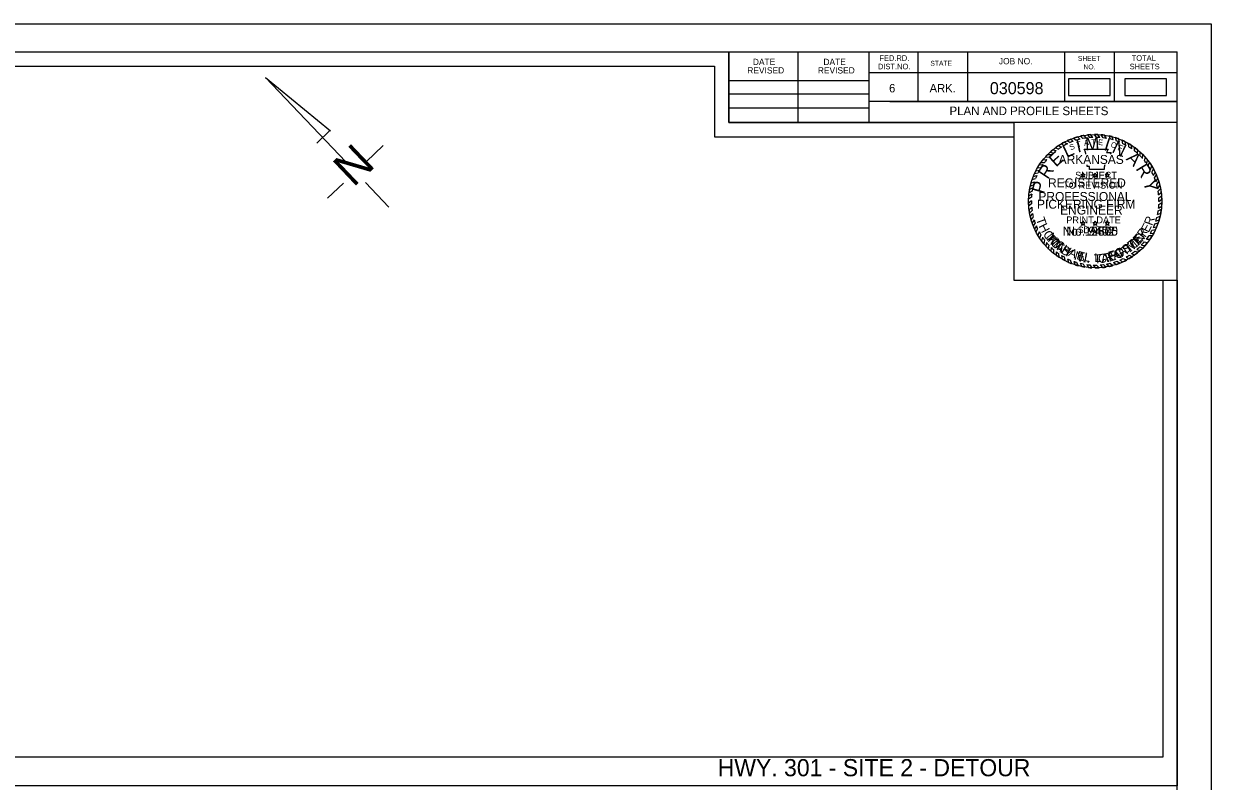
# Model space of a CAD drawing. Extents: x 816090 to 819714, y 1801340 to 1803641.
# Drawn here: x 818885 to 819714, y 1801878 to 1802407 of the extents above; entities that cross this region are included whole.
import ezdxf

# ---------------------------------------------------------------- set-up
doc = ezdxf.new("R2010")
doc.units = 0
for name, color, linetype in [('R_Border', 7, 'Continuous'), ('R_Border Notes', 7, 'Continuous'), ('R_Border Title', 7, 'Continuous'), ('R_Draft', 7, 'Continuous'), ('R_No Plot', 7, 'Continuous'), ('R_Vert Alg Annot', 7, 'Continuous'), ('STAMP_PE_CRAFTON', 7, 'Continuous'), ('STAMP_PE_FOSTER', 7, 'Continuous'), ('STAMP_PE_SEAL-INFO', 7, 'Continuous'), ('STAMP_PE_TAEGTMEYER', 7, 'Continuous'), ('STAMP_PE_TXT', 7, 'Continuous'), ('STAMP_PRELIMINARY', 7, 'Continuous')]:
    doc.layers.add(name, color=color, linetype=linetype)

msp = doc.modelspace()

# ---------------------------------------------------------------- linework, layer by layer
at = {"layer": 'R_Border'}
for p, q in [((818109.59, 1802387.13), (819690.49, 1802387.13)), ((819377.29, 1802337.73), (819377.29, 1802387.13)), ((819425.69, 1802337.73), (819425.69, 1802387.13)), ((819474.99, 1802387.13), (819474.99, 1802337.73)), ((819509.19, 1802387.13), (819509.19, 1802352.43)), ((819543.89, 1802387.13), (819543.89, 1802352.43)), ((819611.79, 1802387.13), (819611.79, 1802352.43)), ((819646.49, 1802387.13), (819646.49, 1802352.43)), ((819690.49, 1801359.83), (819690.49, 1802387.13)), ((819377.29, 1802367.03), (819474.99, 1802367.03)), ((819690.49, 1802372.43), (819474.99, 1802372.43)), ((819690.49, 1802372.53), (819690.49, 1802372.53)), ((819377.29, 1802357.73), (819474.99, 1802357.73)), ((819690.49, 1802352.43), (819474.99, 1802352.43)), ((819489.79, 1802352.43), (819690.49, 1802352.43)), ((819377.29, 1802348.03), (819474.99, 1802348.03)), ((819690.49, 1802337.73), (819377.29, 1802337.73))]:
    msp.add_line(p, q, dxfattribs=at)
at = {"layer": 'R_Draft'}
for p, q in [((819053.53, 1802369.08), (819098.93, 1802331.97)), ((819109.63, 1802310.17), (819053.53, 1802369.08)), ((819089.27, 1802323.37), (819098.63, 1802332.28)), ((819123.68, 1802310.31), (819135.62, 1802321.67)), ((819096.87, 1802284.77), (819108.04, 1802295.41)), ((819139.72, 1802278.56), (819123.23, 1802295.89))]:
    msp.add_line(p, q, dxfattribs=at)
at = {"layer": 'R_No Plot'}
msp.add_line((818047.58, 1802406.6), (819714.25, 1802406.6), dxfattribs=at)
for points in [[(818047.58, 1802406.62), (819714.28, 1802406.62), (819714.28, 1801339.93), (818047.58, 1801339.93)], [(819377.29, 1802387.13), (819377.29, 1802337.73), (819457.85, 1802337.73), (819576.4, 1802337.73), (819576.4, 1802227.73), (819690.49, 1802227.73), (819690.49, 1801874.53), (818109.59, 1801874.53), (818109.59, 1802387.13)], [(819680.49, 1801894.53), (818119.59, 1801894.53), (818119.59, 1802377.13), (819367.29, 1802377.13), (819367.29, 1802327.73), (819576.4, 1802327.73), (819576.4, 1802227.73), (819680.49, 1802227.73)], [(819680.49, 1801894.53), (818119.59, 1801894.53), (818119.59, 1802377.13), (819367.29, 1802377.13), (819367.29, 1802327.73), (819576.4, 1802327.73), (819576.4, 1802227.73), (819680.49, 1802227.73)], [(819680.49, 1801894.53), (818119.59, 1801894.53), (818119.59, 1802377.13), (819367.29, 1802377.13), (819367.29, 1802327.73), (819576.4, 1802327.73), (819576.4, 1802227.73), (819680.49, 1802227.73)], [(819690.49, 1802337.73), (819576.4, 1802337.73), (819576.4, 1802227.73), (819690.49, 1802227.73)]]:
    msp.add_lwpolyline(points, close=True, dxfattribs=at)
at = {"layer": 'R_Vert Alg Annot'}
for points in [[(819614.55, 1802356.65), (819643.72, 1802356.65), (819643.72, 1802368.2), (819614.55, 1802368.2)], [(819653.9, 1802356.65), (819683.07, 1802356.65), (819683.07, 1802368.2), (819653.9, 1802368.2)]]:
    msp.add_lwpolyline(points, close=True, dxfattribs=at)
at = {"layer": 'STAMP_PE_SEAL-INFO'}
for p, q in [((819613.7, 1802325.07), (819615.65, 1802323.7)), ((819616.24, 1802326.15), (819617.71, 1802324.52)), ((819617.98, 1802326.79), (819619.88, 1802325.26)), ((819620.93, 1802327.7), (819622.37, 1802325.96)), ((819622.87, 1802328.18), (819624.65, 1802326.47)), ((819625.28, 1802328.67), (819626.78, 1802326.83)), ((819627.86, 1802329.03), (819629.27, 1802327.12)), ((819631.54, 1802327.26), (819629.98, 1802329.23)), ((819634.03, 1802327.29), (819632.63, 1802329.34)), ((819636.32, 1802327.18), (819635.03, 1802329.3)), ((819638.85, 1802326.93), (819637.39, 1802329.15)), ((819640.98, 1802326.61), (819639.69, 1802328.88)), ((819643.79, 1802326.01), (819642.92, 1802328.31)), ((819645.8, 1802325.47), (819645, 1802327.82)), ((819648.05, 1802324.74), (819647.35, 1802327.13)), ((819650.15, 1802323.94), (819649.42, 1802326.42)), ((819652.45, 1802322.91), (819651.94, 1802325.4)), ((819654.68, 1802321.76), (819654.25, 1802324.31)), ((819601.67, 1802317.07), (819603.96, 1802316.38)), ((819603.38, 1802318.57), (819606.03, 1802318.07)), ((819605.27, 1802320.21), (819607.55, 1802319.18)), ((819607.37, 1802321.54), (819609.58, 1802320.53)), ((819609.31, 1802322.76), (819611.47, 1802321.65)), ((819611.55, 1802324.01), (819613.86, 1802322.89)), ((819625.54, 1802319.18), (819642.27, 1802319.18)), ((819626.15, 1802317.65), (819625.54, 1802319.18)), ((819626.67, 1802316.16), (819626.15, 1802317.65)), ((819626.71, 1802315.58), (819626.67, 1802316.16)), ((819642.27, 1802319.18), (819641.14, 1802316.72)), ((819641.14, 1802316.72), (819644.3, 1802316.72)), ((819644.3, 1802316.72), (819643.58, 1802315.58)), ((819656.62, 1802320.63), (819656.42, 1802323.13)), ((819658.79, 1802319.2), (819658.64, 1802321.77)), ((819660.59, 1802317.86), (819660.77, 1802320.3)), ((819662.83, 1802316), (819662.92, 1802318.62)), ((819664.39, 1802314.54), (819664.74, 1802317.03)), ((819594.08, 1802308.11), (819596.66, 1802308.28)), ((819595.26, 1802309.83), (819597.78, 1802309.8)), ((819596.65, 1802311.68), (819599.39, 1802311.79)), ((819598.38, 1802313.73), (819600.98, 1802313.54)), ((819599.99, 1802315.45), (819602.71, 1802315.25)), ((819627.66, 1802307.04), (819627.53, 1802308.13)), ((819639.85, 1802308.13), (819639.46, 1802306.58)), ((819666.18, 1802312.67), (819666.52, 1802315.3)), ((819667.55, 1802311.09), (819668.24, 1802313.45)), ((819669.17, 1802309.01), (819669.85, 1802311.5)), ((819670.27, 1802307.43), (819671.16, 1802309.75)), ((819589.84, 1802299.88), (819592.36, 1802300.61)), ((819590.76, 1802302.04), (819593.27, 1802302.56)), ((819591.7, 1802303.99), (819594.19, 1802304.31)), ((819592.85, 1802306.1), (819595.3, 1802306.2)), ((819629.23, 1802307.04), (819627.66, 1802307.04)), ((819629.23, 1802304.89), (819629.23, 1802307.04)), ((819639.38, 1802304.89), (819629.23, 1802304.89)), ((819639.46, 1802306.58), (819639.38, 1802304.89)), ((819671.81, 1802304.94), (819672.73, 1802307.4)), ((819672.81, 1802303.11), (819673.94, 1802305.33)), ((819673.97, 1802300.69), (819675.1, 1802303.12)), ((819674.67, 1802299.01), (819675.99, 1802301.17)), ((819589.6, 1802292.06), (819587.27, 1802290.82)), ((819587.78, 1802293.3), (819590.13, 1802294.26)), ((819588.3, 1802295.33), (819590.69, 1802296.18)), ((819589.09, 1802297.85), (819591.51, 1802298.53)), ((819675.64, 1802296.26), (819677, 1802298.63)), ((819676.18, 1802294.44), (819677.65, 1802296.7)), ((819676.85, 1802291.64), (819678.44, 1802293.88)), ((819677.19, 1802289.74), (819678.96, 1802291.51)), ((819588.7, 1802285.47), (819586.59, 1802284.18)), ((819588.61, 1802283), (819586.59, 1802281.32)), ((819588.88, 1802287.59), (819586.7, 1802286.19)), ((819589.17, 1802289.77), (819586.95, 1802288.66)), ((819677.52, 1802287.2), (819679.39, 1802288.88)), ((819677.68, 1802285.11), (819679.64, 1802286.57)), ((819677.75, 1802282.52), (819679.77, 1802284.13)), ((819588.65, 1802280.97), (819586.69, 1802279.34)), ((819588.81, 1802278.49), (819586.96, 1802276.71)), ((819589.07, 1802276.34), (819587.3, 1802274.48)), ((819676.79, 1802273.52), (819679.06, 1802274.5)), ((819677.24, 1802276.02), (819679.45, 1802277.12)), ((819677.49, 1802277.96), (819679.66, 1802279.24)), ((819677.69, 1802280.49), (819679.79, 1802281.88)), ((819589.47, 1802274.05), (819587.77, 1802272.21)), ((819589.93, 1802271.95), (819588.37, 1802269.88)), ((819590.55, 1802269.72), (819589.08, 1802267.63)), ((819591.26, 1802267.6), (819589.85, 1802265.54)), ((819674.84, 1802266.89), (819677.25, 1802267.54)), ((819675.51, 1802268.79), (819677.96, 1802269.79)), ((819676.25, 1802271.26), (819678.61, 1802272.27)), ((819592.09, 1802265.47), (819590.78, 1802263.36)), ((819592.95, 1802263.55), (819591.81, 1802261.25)), ((819594.12, 1802261.26), (819593.17, 1802258.81)), ((819595.3, 1802259.24), (819594.38, 1802256.89)), ((819670.74, 1802258.74), (819673.13, 1802258.71)), ((819671.6, 1802260.14), (819674.11, 1802260.41)), ((819672.96, 1802262.64), (819675.4, 1802262.98)), ((819673.77, 1802264.32), (819676.21, 1802264.8)), ((819596.31, 1802257.69), (819595.76, 1802254.93)), ((819597.72, 1802255.73), (819597.21, 1802253.08)), ((819599.24, 1802253.85), (819598.8, 1802251.25)), ((819600.75, 1802252.16), (819600.44, 1802249.55)), ((819602.36, 1802250.53), (819602.21, 1802247.89)), ((819664.32, 1802250.84), (819666.52, 1802250.15)), ((819665.59, 1802252.13), (819667.98, 1802251.71)), ((819667.51, 1802254.3), (819669.81, 1802253.9)), ((819669.05, 1802256.27), (819671.57, 1802256.28)), ((819604.08, 1802248.97), (819604.07, 1802246.32)), ((819605.88, 1802247.5), (819605.98, 1802244.87)), ((819607.57, 1802246.25), (819607.76, 1802243.66)), ((819609.71, 1802244.84), (819610.01, 1802242.28)), ((819611.46, 1802243.81), (819611.92, 1802241.24)), ((819613.87, 1802242.56), (819614.65, 1802239.95)), ((819615.73, 1802241.72), (819616.59, 1802239.16)), ((819650.5, 1802241.66), (819652.62, 1802240.36)), ((819652.8, 1802242.71), (819655.22, 1802241.65)), ((819654.84, 1802243.77), (819656.92, 1802242.61)), ((819656.91, 1802245), (819659.16, 1802244.02)), ((819658.63, 1802246.14), (819660.82, 1802245.19)), ((819660.93, 1802247.85), (819663.27, 1802247.13)), ((819662.29, 1802248.98), (819664.64, 1802248.33)), ((819618.19, 1802240.75), (819619.24, 1802238.25)), ((819620.24, 1802240.08), (819621.37, 1802237.63)), ((819622.78, 1802239.39), (819623.84, 1802237.06)), ((819624.77, 1802238.96), (819626, 1802236.67)), ((819627.27, 1802238.55), (819628.47, 1802236.35)), ((819629.45, 1802238.31), (819630.82, 1802236.17)), ((819631.87, 1802238.18), (819633.39, 1802236.11)), ((819634.17, 1802238.17), (819635.89, 1802236.19)), ((819636.77, 1802238.3), (819638.4, 1802236.4)), ((819638.96, 1802238.53), (819640.82, 1802236.74)), ((819641.18, 1802238.88), (819643.13, 1802237.19)), ((819643.65, 1802239.4), (819645.54, 1802237.78)), ((819645.94, 1802240.02), (819648.03, 1802238.54)), ((819648.41, 1802240.84), (819650.62, 1802239.5))]:
    msp.add_line(p, q, dxfattribs=at)
for radius, start, end in [(46.61, 111.31242, 114.70259), (44.57, 110.30864, 113.16588), (46.61, 105.23389, 109.03519), (44.57, 104.03521, 107.36155), (46.61, 99.75254, 102.77648), (44.57, 98.25799, 101.03289), (46.61, 93.93815, 96.55172), (44.57, 92.11016, 95.03666), (46.61, 87.72979, 90.67067), (44.57, 85.96279, 88.9097), (46.61, 81.97315, 84.82355), (44.57, 79.92642, 82.69597), (46.61, 75.31251, 77.94263), (44.57, 73.55748, 76.23144), (46.61, 69.60611, 72.30577), (44.57, 67.62483, 70.50398), (46.61, 63.13288, 66.2704), (46.61, 129.73259, 132.53764), (44.57, 127.52969, 130.96829), (46.61, 123.61993, 126.59063), (44.57, 121.97456, 125.11001), (46.61, 117.65441, 120.80988), (44.57, 115.68692, 119.15827), (44.57, 61.15575, 64.37837), (46.61, 56.90029, 60.09423), (44.57, 54.92383, 58.27016), (44.57, 48.30163, 52.03953), (46.61, 50.3492, 53.71593), (46.61, 44.3405, 47.39292), (46.61, 147.00719, 149.89904), (46.61, 141.60556, 144.44865), (44.57, 145.01972, 148.21036), (44.57, 139.30101, 142.58729), (46.61, 135.40208, 138.30314), (44.57, 133.13306, 136.25623), (44.57, 42.22116, 45.55119), (44.57, 36.13503, 39.53106), (46.61, 38.12472, 41.23157), (46.61, 31.96138, 35.42937), (46.61, 158.40766, 161.07015), (46.61, 152.86398, 155.51889), (44.57, 156.34018, 159.23194), (44.57, 151.03153, 153.57304), (44.57, 29.90321, 33.66454), (44.57, 23.77322, 27.22114), (46.61, 25.93909, 29.01247), (46.61, 19.95381, 23.31409), (46.61, 164.3068, 166.89395), (44.57, 167.90481, 170.90393), (44.57, 162.43309, 165.00133), (44.57, 17.68022, 21.42509), (44.57, 11.54445, 15.23639), (46.61, 13.84205, 17.44468), (46.61, 7.58519, 10.86211), (46.61, 175.74093, 178.2066), (46.61, 170.0003, 172.68778), (44.57, 179.64537, 182.26333), (44.57, 173.73, 176.47337), (44.57, 5.7599, 9.06056), (44.57, 359.73289, 3.06392), (46.61, 1.72155, 4.72681), (46.61, 181.72508, 184.16255), (46.61, 187.42037, 190.19271), (44.57, 185.45389, 188.23401), (44.57, 348.07782, 351.34355), (44.57, 353.86319, 357.12742), (46.61, 349.83047, 353.08845), (46.61, 355.71562, 358.95694), (46.61, 193.03695, 195.99732), (46.61, 198.89671, 201.62812), (44.57, 191.22736, 193.98583), (44.57, 196.96751, 199.83526), (44.57, 335.6038, 339.18578), (44.57, 341.77699, 345.09248), (46.61, 337.38367, 340.99332), (46.61, 343.89247, 347.03502), (46.61, 204.54793, 207.43282), (44.57, 202.77613, 205.47915), (46.61, 210.86355, 213.65709), (44.57, 208.78826, 211.79343), (44.57, 323.58513, 327.44069), (46.61, 325.44052, 328.98725), (44.57, 329.55488, 333.20757), (46.61, 331.40371, 334.93315), (46.61, 216.61154, 219.49098), (44.57, 214.18375, 217.27474), (46.61, 222.47995, 225.38008), (44.57, 220.39088, 223.30564), (44.57, 226.24938, 229.24068), (44.57, 310.77436, 314.31605), (46.61, 312.45177, 315.66328), (44.57, 316.65308, 320.37109), (46.61, 318.28455, 321.80429), (46.61, 228.36648, 231.34802), (44.57, 232.22904, 234.93361), (46.61, 234.29502, 236.94517), (44.57, 238.22227, 240.83529), (46.61, 240.1977, 242.86128), (44.57, 244.32043, 246.94859), (44.57, 292.87452, 296.11851), (46.61, 294.64808, 298.21662), (44.57, 299.07679, 302.17235), (46.61, 300.62101, 303.87026), (44.57, 304.82299, 308.51428), (46.61, 306.37206, 310.20799), (46.61, 246.57598, 249.15579), (44.57, 250.34912, 253.12157), (46.61, 252.59667, 255.32518), (44.57, 256.50505, 259.11916), (46.61, 258.44328, 261.13983), (44.57, 262.37828, 265.20115), (46.61, 264.19784, 267.10092), (44.57, 268.3215, 271.27698), (46.61, 270.25484, 273.33609), (44.57, 274.61565, 277.44863), (46.61, 276.42389, 279.43574), (44.57, 280.34588, 283.58137), (46.61, 282.31994, 285.37019), (44.57, 286.64233, 289.97826), (46.61, 288.57086, 291.97334)]:
    msp.add_arc((819633.18, 1802282.73), radius, start, end, dxfattribs=at)
at = {"layer": 'STAMP_PE_TXT'}
for p, q in [((819624.08, 1802300.58), (819623.09, 1802301.3)), ((819623.09, 1802301.3), (819624.31, 1802301.3)), ((819623.7, 1802299.42), (819624.08, 1802300.58)), ((819624.69, 1802300.14), (819623.7, 1802299.42)), ((819624.31, 1802301.3), (819624.69, 1802302.47)), ((819624.69, 1802302.47), (819625.07, 1802301.3)), ((819625.68, 1802299.42), (819624.69, 1802300.14)), ((819625.07, 1802301.3), (819626.3, 1802301.3)), ((819626.3, 1802301.3), (819625.3, 1802300.58)), ((819625.3, 1802300.58), (819625.68, 1802299.42)), ((819632.57, 1802300.58), (819631.58, 1802301.3)), ((819631.58, 1802301.3), (819632.8, 1802301.3)), ((819632.19, 1802299.42), (819632.57, 1802300.58)), ((819633.18, 1802300.14), (819632.19, 1802299.42)), ((819632.8, 1802301.3), (819633.18, 1802302.47)), ((819633.18, 1802302.47), (819633.56, 1802301.3)), ((819634.17, 1802299.42), (819633.18, 1802300.14)), ((819633.56, 1802301.3), (819634.79, 1802301.3)), ((819634.79, 1802301.3), (819633.79, 1802300.58)), ((819633.79, 1802300.58), (819634.17, 1802299.42)), ((819641.06, 1802300.58), (819640.07, 1802301.3)), ((819640.07, 1802301.3), (819641.29, 1802301.3)), ((819640.68, 1802299.42), (819641.06, 1802300.58)), ((819641.67, 1802300.14), (819640.68, 1802299.42)), ((819641.29, 1802301.3), (819641.67, 1802302.47)), ((819641.67, 1802302.47), (819642.05, 1802301.3)), ((819642.66, 1802299.42), (819641.67, 1802300.14)), ((819642.05, 1802301.3), (819643.27, 1802301.3)), ((819643.27, 1802301.3), (819642.28, 1802300.58)), ((819642.28, 1802300.58), (819642.66, 1802299.42)), ((819624.08, 1802267.05), (819623.09, 1802267.77)), ((819623.09, 1802267.77), (819624.31, 1802267.77)), ((819623.7, 1802265.88), (819624.08, 1802267.05)), ((819624.69, 1802266.6), (819623.7, 1802265.88)), ((819624.31, 1802267.77), (819624.69, 1802268.93)), ((819624.69, 1802268.93), (819625.07, 1802267.77)), ((819625.68, 1802265.88), (819624.69, 1802266.6)), ((819625.07, 1802267.77), (819626.3, 1802267.77)), ((819626.3, 1802267.77), (819625.3, 1802267.05)), ((819625.3, 1802267.05), (819625.68, 1802265.88)), ((819632.57, 1802267.05), (819631.58, 1802267.77)), ((819631.58, 1802267.77), (819632.8, 1802267.77)), ((819632.19, 1802265.88), (819632.57, 1802267.05)), ((819633.18, 1802266.6), (819632.19, 1802265.88)), ((819632.8, 1802267.77), (819633.18, 1802268.93)), ((819633.18, 1802268.93), (819633.56, 1802267.77)), ((819634.17, 1802265.88), (819633.18, 1802266.6)), ((819633.56, 1802267.77), (819634.79, 1802267.77)), ((819634.79, 1802267.77), (819633.79, 1802267.05)), ((819633.79, 1802267.05), (819634.17, 1802265.88)), ((819641.06, 1802267.05), (819640.07, 1802267.77)), ((819640.07, 1802267.77), (819641.29, 1802267.77)), ((819640.68, 1802265.88), (819641.06, 1802267.05)), ((819641.67, 1802266.6), (819640.68, 1802265.88)), ((819641.29, 1802267.77), (819641.67, 1802268.93)), ((819641.67, 1802268.93), (819642.05, 1802267.77)), ((819642.66, 1802265.88), (819641.67, 1802266.6)), ((819642.05, 1802267.77), (819643.27, 1802267.77)), ((819643.27, 1802267.77), (819642.28, 1802267.05)), ((819642.28, 1802267.05), (819642.66, 1802265.88))]:
    msp.add_line(p, q, dxfattribs=at)
at = {"layer": 'STAMP_PRELIMINARY'}
msp.add_circle((819633.18, 1802282.73), 46.61, dxfattribs=at)

# ---------------------------------------------------------------- texts
at = {"layer": 'R_Border'}
for s, height, p in [('FED.RD.', 3.91, (819482.39, 1802380.73)), ('JOB NO.', 4.396, (819565.89, 1802378.33)), ('SHEET', 3.42, (819621.09, 1802380.73)), ('TOTAL', 3.91, (819658.69, 1802380.73)), ('REVISED', 4.396, (819390.08, 1802371.91)), ('DATE', 4.396, (819393.98, 1802377.81)), ('REVISED', 4.396, (819439.38, 1802371.91)), ('DATE', 4.396, (819443.28, 1802377.81)), ('DIST.NO.', 3.91, (819481.39, 1802374.83)), ('STATE', 3.42, (819517.99, 1802377.33)), ('NO.', 3.42, (819624.99, 1802374.83)), ('SHEETS', 3.91, (819657.29, 1802374.83)), ('6', 5.86, (819489.19, 1802358.73)), ('ARK.', 5.861, (819517.49, 1802358.73))]:
    msp.add_text(s, height=height, dxfattribs=at).set_placement(p)
at = {"layer": 'R_Border Notes'}
for s, height, p in [('030598', 8.4, (819559.59, 1802357.46)), ('PLAN AND PROFILE SHEETS', 6, (819531.4, 1802342.82))]:
    msp.add_text(s, height=height, dxfattribs=at).set_placement(p)
at = {"layer": 'R_Border Title'}
msp.add_text('HWY. 301 - SITE 2 - DETOUR', height=12, dxfattribs=at).set_placement((819369.46, 1801881.28))
at = {"layer": 'R_Draft'}
msp.add_text('N', height=23.27, rotation=43.59785, dxfattribs=at).set_placement((819114.79, 1802291.95))
at = {"layer": 'STAMP_PE_CRAFTON'}
for s, rotation, p in [('T', 310.74416, (819598.01, 1802257.21)), ('N', 49.24107, (819664.59, 1802252.84)), ('O', 317.64216, (819601.35, 1802253.16)), ('N', 324.45371, (819605.58, 1802249.23)), ('Y', 331.16864, (819610.74, 1802245.65)), ('F', 28.78207, (819651.49, 1802243.37)), ('T', 34.11362, (819656.06, 1802245.92)), ('O', 41.83906, (819660.36, 1802248.93)), ('N', 347.47515, (819621.01, 1802241.07)), ('C', 6.01169, (819635.54, 1802239.43)), ('R', 14.81888, (819641.02, 1802240.01)), ('A', 20.51248, (819646.58, 1802241.5)), ('.', 356.89262, (819627.16, 1802239.69))]:
    msp.add_text(s, height=6.25, rotation=rotation, dxfattribs=at).set_placement(p)
msp.add_text('No. 12370', height=6.25, dxfattribs=at).set_placement((819610.49, 1802258.71))
at = {"layer": 'STAMP_PE_FOSTER'}
for s, rotation, p in [('M', 308.33902, (819598.76, 1802257.84)), ('E', 46.96131, (819663.18, 1802252.68)), ('R', 54.5031, (819666.8, 1802256.78)), ('I', 314.18423, (819602.75, 1802253.15)), ('C', 319.87327, (819604.52, 1802251.38)), ('H', 327.72349, (819609.17, 1802247.7)), ('O', 23.71897, (819648.58, 1802243.14)), ('S', 31.72336, (819654.13, 1802245.79)), ('T', 39.41938, (819658.89, 1802248.93)), ('A', 335.72761, (819614.07, 1802244.79)), ('E', 343.5779, (819619.76, 1802242.44)), ('L', 350.81148, (819625.05, 1802241.05)), ('L', 1.26658, (819632.75, 1802240.27)), ('.', 6.80354, (819637.98, 1802240.56)), ('F', 15.86908, (819643.36, 1802241.5))]:
    msp.add_text(s, height=6, rotation=rotation, dxfattribs=at).set_placement(p)
msp.add_text('No. 9402', height=6.25, dxfattribs=at).set_placement((819613.11, 1802258.71))
at = {"layer": 'STAMP_PE_TAEGTMEYER'}
for s, rotation, p in [('T', 289.64597, (819591.65, 1802270.28)), ('H', 296.73386, (819593.45, 1802265.35)), ('E', 63.0984, (819670.41, 1802260.39)), ('R', 69.57001, (819672.91, 1802265.3)), ('O', 303.77078, (819596.42, 1802259.81)), ('M', 314.20329, (819599.69, 1802255.06)), ('E', 46.80938, (819663.37, 1802251.61)), ('Y', 53.99864, (819667.07, 1802255.69)), ('A', 321.0594, (819604.5, 1802250.24)), ('S', 327.82385, (819608.63, 1802247.02)), ('T', 31.46601, (819653.68, 1802244.5)), ('M', 39.30005, (819658.17, 1802247.22)), ('N', 344.27273, (819618.11, 1802241.98)), ('T', 3.00609, (819632.5, 1802239.33)), ('A', 8.98261, (819637.73, 1802239.61)), ('E', 17.68363, (819642.93, 1802240.38)), ('G', 23.30524, (819648.18, 1802242.04)), ('.', 350.64643, (819624.18, 1802240.32))]:
    msp.add_text(s, height=6.25, rotation=rotation, dxfattribs=at).set_placement(p)
msp.add_text('No. 19605', height=6.25, dxfattribs=at).set_placement((819610.49, 1802258.71))
at = {"layer": 'STAMP_PE_TXT'}
for s, rotation, p in [('T', 16.311, (819620.79, 1802320.11)), ('A', 9.0679, (819625.6, 1802321.37)), ('T', 1.82479, (819630.53, 1802322.02)), ('E', 355.20019, (819635.08, 1802322.06)), ('S', 23.5541, (819616.17, 1802318.24)), ('O', 342.25065, (819643.72, 1802320.68)), ('F', 335.00755, (819648.54, 1802318.99))]:
    msp.add_text(s, height=3.91, rotation=rotation, dxfattribs=at).set_placement(p)
for s, p in [('ARKANSAS', (819607.64, 1802308.78)), ('REGISTERED', (819600.26, 1802292.43)), ('PROFESSIONAL', (819593.52, 1802282.92)), ('ENGINEER', (819608.72, 1802273.42))]:
    msp.add_text(s, height=6.25, dxfattribs=at).set_placement(p)
at = {"layer": 'STAMP_PRELIMINARY'}
for s, rotation, p in [('I', 12.52485, (819620.87, 1802316.66)), ('M', 3.10738, (819626.36, 1802318.2)), ('I', 342.31637, (819638.7, 1802318.54)), ('N', 333.9382, (819644.23, 1802317.17)), ('E', 42.35784, (819605.81, 1802306.21)), ('L', 25.51305, (819613.22, 1802312.86)), ('A', 315.65789, (819654.4, 1802312.04)), ('R', 56.22922, (819600.03, 1802297.54)), ('R', 301.38306, (819661.24, 1802305.47)), ('P', 73.91301, (819597.29, 1802287.43)), ('Y', 283.25926, (819666.69, 1802296.54))]:
    msp.add_text(s, height=9, rotation=rotation, dxfattribs=at).set_placement(p)
for s, height, p in [('SUBJECT', 4.8, (819619.18, 1802298.47)), ('TO REVISION', 4.8, (819610.86, 1802291.55)), ('PICKERING FIRM', 6.25, (819592.55, 1802277.54)), ('PRINT DATE', 4.8, (819612.97, 1802267.3)), ('$DATE$', 4.8, (819621.35, 1802260.38))]:
    msp.add_text(s, height=height, dxfattribs=at).set_placement(p)

doc.saveas('drawing.dxf')
